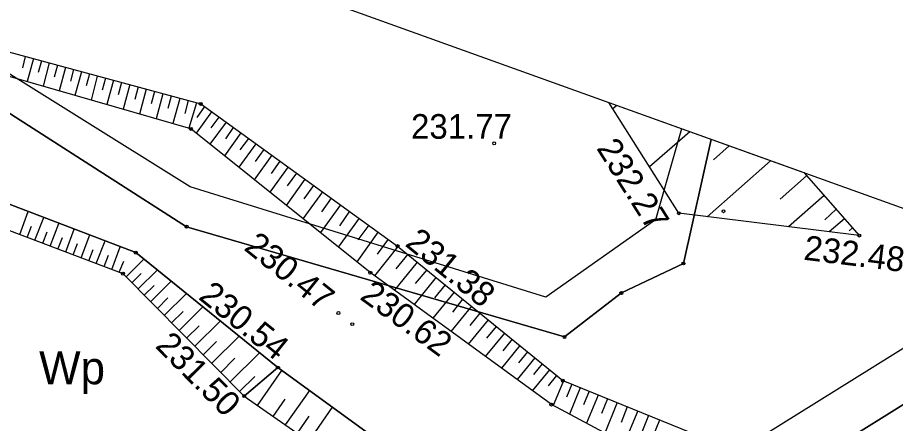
# Model space of a CAD drawing. Extents: x 6596400 to 6597200, y 5539751 to 5540251.
# Drawn here: x 6596761.51 to 6596788.23, y 5540103.13 to 5540115.5 of the extents above; entities that cross this region are included whole.
import ezdxf

# ---------------------------------------------------------------- set-up
doc = ezdxf.new("R2010")
doc.units = 0
for name, color, linetype in [('000 Inne (niezydentyfikowane)', 7, 'Continuous'), ('140-Punkty robocze', 7, 'Continuous'), ('203-punkt graniczny', 7, 'Continuous'), ('210-oznaczenie konturu użytku gruntowego', 7, 'Continuous'), ('217-kontur klasyfikacyjny', 7, 'Continuous'), ('218-kontur użytku gruntowego', 7, 'Continuous'), ('219-działka ewidencyjna', 7, 'Continuous'), ('Linia obszaru zagospodarowania terenu', 7, 'Continuous'), ('pikieta sztuczna', 7, 'Continuous'), ('pikieta sztuczna-Atr2', 7, 'Continuous'), ('skarpa nieumocniona', 7, 'Continuous'), ('skarpa umocniona', 7, 'Continuous'), ('woda płynąca', 7, 'Continuous'), ('Zakres', 7, 'Continuous')]:
    doc.layers.add(name, color=color, linetype=linetype)

# ---------------------------------------------------------------- blocks, each defined once
blk = doc.blocks.new('203')
blk.add_circle((0, 0), 0.045)
blk = doc.blocks.new('PIKIETA')
blk.add_circle((0, 0), 0.045)
blk = doc.blocks.new('PW01')
blk.add_circle((0, 0), 0.045)

msp = doc.modelspace()

# ---------------------------------------------------------------- linework, layer by layer
at = {"layer": '000 Inne (niezydentyfikowane)'}
for p, q in [((6596761.75, 5540114.32), (6596761.66, 5540113.97)), ((6596762, 5540114.25), (6596761.81, 5540113.55)), ((6596762.24, 5540114.18), (6596762.14, 5540113.83)), ((6596762.48, 5540114.12), (6596762.29, 5540113.41)), ((6596762.73, 5540114.05), (6596762.63, 5540113.69)), ((6596762.97, 5540113.98), (6596762.78, 5540113.27)), ((6596763.22, 5540113.92), (6596763.12, 5540113.56)), ((6596763.46, 5540113.85), (6596763.26, 5540113.13)), ((6596763.7, 5540113.79), (6596763.6, 5540113.42)), ((6596763.94, 5540113.72), (6596763.75, 5540112.99)), ((6596764.19, 5540113.66), (6596764.09, 5540113.29)), ((6596764.43, 5540113.59), (6596764.23, 5540112.85)), ((6596764.68, 5540113.52), (6596764.58, 5540113.15)), ((6596764.93, 5540113.46), (6596764.73, 5540112.71)), ((6596765.18, 5540113.39), (6596765.08, 5540113.01)), ((6596765.43, 5540113.32), (6596765.22, 5540112.56)), ((6596765.68, 5540113.25), (6596765.58, 5540112.87)), ((6596765.94, 5540113.18), (6596765.73, 5540112.42)), ((6596766.19, 5540113.11), (6596766.09, 5540112.73)), ((6596766.45, 5540113.04), (6596766.24, 5540112.27)), ((6596766.71, 5540112.97), (6596766.6, 5540112.58)), ((6596766.96, 5540112.9), (6596766.73, 5540112.13)), ((6596767.42, 5540112.63), (6596766.95, 5540111.98)), ((6596767.2, 5540112.79), (6596766.97, 5540112.46)), ((6596779.748, 5540112.823), (6596779.63, 5540112.72)), ((6596767.64, 5540112.47), (6596767.4, 5540112.14)), ((6596767.86, 5540112.31), (6596767.37, 5540111.64)), ((6596768.08, 5540112.15), (6596767.84, 5540111.81)), ((6596768.31, 5540111.99), (6596767.81, 5540111.29)), ((6596768.54, 5540111.82), (6596768.28, 5540111.47)), ((6596781.972, 5540112.024), (6596780.75, 5540110.95)), ((6596768.77, 5540111.65), (6596768.25, 5540110.94)), ((6596783.174, 5540111.591), (6596782.7, 5540111.17)), ((6596769.25, 5540111.31), (6596768.72, 5540110.56)), ((6596769.01, 5540111.48), (6596768.75, 5540111.12)), ((6596769.5, 5540111.13), (6596769.23, 5540110.75)), ((6596784.433, 5540111.138), (6596782.5, 5540109.43)), ((6596769.75, 5540110.95), (6596769.19, 5540110.18)), ((6596770, 5540110.76), (6596769.72, 5540110.37)), ((6596770.26, 5540110.58), (6596769.69, 5540109.78)), ((6596785.53, 5540110.68), (6596784.72, 5540109.97)), ((6596770.79, 5540110.19), (6596770.2, 5540109.37)), ((6596770.52, 5540110.39), (6596770.23, 5540109.98)), ((6596771.06, 5540110), (6596770.76, 5540109.58)), ((6596786.06, 5540110.08), (6596784.98, 5540109.13)), ((6596771.34, 5540109.8), (6596770.73, 5540108.95)), ((6596786.43, 5540109.66), (6596786.08, 5540109.34)), ((6596771.91, 5540109.39), (6596771.27, 5540108.51)), ((6596771.62, 5540109.6), (6596771.31, 5540109.16)), ((6596772.2, 5540109.18), (6596771.87, 5540108.73)), ((6596786.68, 5540109.37), (6596786.22, 5540108.97)), ((6596772.49, 5540108.97), (6596771.84, 5540108.06)), ((6596786.92, 5540109.09), (6596786.82, 5540109)), ((6596772.79, 5540108.75), (6596772.46, 5540108.29)), ((6596773.09, 5540108.53), (6596772.38, 5540107.63)), ((6596773.39, 5540108.29), (6596773.03, 5540107.85)), ((6596773.68, 5540108.05), (6596772.98, 5540107.19)), ((6596773.97, 5540107.82), (6596773.62, 5540107.4)), ((6596774.25, 5540107.59), (6596773.58, 5540106.76)), ((6596774.53, 5540107.36), (6596774.2, 5540106.96)), ((6596774.8, 5540107.14), (6596774.15, 5540106.34)), ((6596775.06, 5540106.92), (6596774.75, 5540106.53)), ((6596775.33, 5540106.71), (6596774.7, 5540105.94)), ((6596775.58, 5540106.5), (6596775.28, 5540106.12)), ((6596775.84, 5540106.29), (6596775.23, 5540105.55)), ((6596776.08, 5540106.09), (6596775.79, 5540105.73)), ((6596776.33, 5540105.89), (6596775.75, 5540105.18)), ((6596776.57, 5540105.7), (6596776.28, 5540105.35)), ((6596776.8, 5540105.51), (6596776.24, 5540104.82)), ((6596777.26, 5540105.13), (6596776.72, 5540104.47)), ((6596777.03, 5540105.32), (6596776.76, 5540104.98)), ((6596777.48, 5540104.95), (6596777.22, 5540104.63)), ((6596777.7, 5540104.77), (6596777.18, 5540104.13)), ((6596777.92, 5540104.6), (6596777.66, 5540104.28)), ((6596778.13, 5540104.43), (6596777.82, 5540103.68)), ((6596778.38, 5540104.33), (6596778.22, 5540103.94)), ((6596778.64, 5540104.22), (6596778.31, 5540103.42)), ((6596778.91, 5540104.12), (6596778.74, 5540103.7)), ((6596779.18, 5540104), (6596778.83, 5540103.14)), ((6596779.47, 5540103.89), (6596779.29, 5540103.44)), ((6596779.76, 5540103.77), (6596779.39, 5540102.84)), ((6596780.07, 5540103.64), (6596779.88, 5540103.16)), ((6596780.39, 5540103.52), (6596779.98, 5540102.52)), ((6596780.72, 5540103.38), (6596780.51, 5540102.87)), ((6596781.05, 5540103.24), (6596780.62, 5540102.18))]:
    msp.add_line(p, q, dxfattribs=at)
for points in [[(6596761.58, 5540108.89), (6596761.84, 5540109.59)], [(6596762.04, 5540108.72), (6596762.31, 5540109.41)], [(6596761.81, 5540108.8), (6596761.94, 5540109.15)], [(6596762.51, 5540108.54), (6596762.77, 5540109.23)], [(6596762.28, 5540108.63), (6596762.41, 5540108.97)], [(6596762.98, 5540108.36), (6596763.24, 5540109.05)], [(6596763.45, 5540108.18), (6596763.71, 5540108.88)], [(6596762.74, 5540108.45), (6596762.88, 5540108.8)], [(6596763.21, 5540108.27), (6596763.34, 5540108.62)], [(6596763.91, 5540108.01), (6596764.18, 5540108.7)], [(6596763.68, 5540108.09), (6596763.81, 5540108.44)], [(6596764.38, 5540107.83), (6596764.64, 5540108.52)], [(6596764.15, 5540107.92), (6596764.28, 5540108.26)], [(6596764.61, 5540107.74), (6596764.75, 5540108.08)], [(6596764.82, 5540107.6), (6596765.36, 5540108.14)], [(6596765.18, 5540107.24), (6596765.76, 5540107.81)], [(6596764.99, 5540107.42), (6596765.28, 5540107.7)], [(6596765.37, 5540107.04), (6596765.67, 5540107.34)], [(6596765.57, 5540106.85), (6596766.19, 5540107.47)], [(6596765.98, 5540106.42), (6596766.66, 5540107.09)], [(6596765.77, 5540106.64), (6596766.09, 5540106.96)], [(6596766.2, 5540106.2), (6596766.55, 5540106.55)], [(6596766.43, 5540105.97), (6596767.15, 5540106.69)], [(6596766.91, 5540105.49), (6596767.69, 5540106.26)], [(6596766.66, 5540105.73), (6596767.04, 5540106.11)], [(6596767.43, 5540104.97), (6596768.26, 5540105.79)], [(6596767.16, 5540105.23), (6596767.57, 5540105.63)], [(6596767.7, 5540104.69), (6596768.13, 5540105.12)], [(6596767.98, 5540104.4), (6596768.88, 5540105.29)], [(6596768.82, 5540103.68), (6596769.56, 5540104.75)], [(6596768.27, 5540104.11), (6596768.74, 5540104.57)], [(6596769.67, 5540103.09), (6596770.41, 5540104.14)], [(6596769.29, 5540103.35), (6596769.66, 5540103.88)], [(6596770.38, 5540102.59), (6596771.1, 5540103.63)], [(6596770.03, 5540102.84), (6596770.39, 5540103.36)]]:
    msp.add_lwpolyline(points, dxfattribs=at)
at = {"layer": '217-kontur klasyfikacyjny'}
for points in [[(6596757.03, 5540115.3), (6596766.66, 5540109.13)], [(6596781.78, 5540108.01), (6596782.625, 5540111.789)], [(6596766.66, 5540109.13), (6596778.16, 5540105.77)], [(6596779.89, 5540107.11), (6596781.78, 5540108.01)], [(6596778.16, 5540105.77), (6596779.89, 5540107.11)], [(6596791.43, 5540105.56), (6596776.03, 5540095.93)]]:
    msp.add_lwpolyline(points, dxfattribs=at)
at = {"layer": '218-kontur użytku gruntowego'}
for points in [[(6596757.03, 5540115.3), (6596766.66, 5540109.13)], [(6596766.66, 5540109.13), (6596757.03, 5540115.3)], [(6596781.78, 5540108.01), (6596782.625, 5540111.789)], [(6596782.625, 5540111.789), (6596781.78, 5540108.01)], [(6596766.66, 5540109.13), (6596778.16, 5540105.77)], [(6596778.16, 5540105.77), (6596766.66, 5540109.13)], [(6596779.89, 5540107.11), (6596781.78, 5540108.01)], [(6596781.78, 5540108.01), (6596779.89, 5540107.11)], [(6596778.16, 5540105.77), (6596779.89, 5540107.11)], [(6596779.89, 5540107.11), (6596778.16, 5540105.77)], [(6596776.03, 5540095.93), (6596791.43, 5540105.56)], [(6596791.43, 5540105.56), (6596776.03, 5540095.93)]]:
    msp.add_lwpolyline(points, dxfattribs=at)
at = {"layer": '219-działka ewidencyjna'}
for points in [[(6596766.66, 5540109.13), (6596757.03, 5540115.3)], [(6596781.78, 5540108.01), (6596782.625, 5540111.789)], [(6596778.16, 5540105.77), (6596766.66, 5540109.13)], [(6596779.89, 5540107.11), (6596781.78, 5540108.01)], [(6596778.16, 5540105.77), (6596779.89, 5540107.11)], [(6596776.03, 5540095.93), (6596791.43, 5540105.56)]]:
    msp.add_lwpolyline(points, dxfattribs=at)
at = {"layer": 'Linia obszaru zagospodarowania terenu'}
for points in [[(6596781.725, 5540112.112), (6596780.93, 5540109.34), (6596777.59, 5540106.98), (6596766.77, 5540110.34), (6596752.84, 5540119.06), (6596742.54, 5540110.89), (6596731.18, 5540096.66), (6596730.7, 5540082.79)], [(6596746.77, 5540082.74), (6596749.37, 5540097.92), (6596757.81, 5540103.76), (6596775.58, 5540097.4), (6596790.99, 5540107), (6596791.128, 5540108.731)]]:
    msp.add_lwpolyline(points, dxfattribs=at)
at = {"layer": 'skarpa nieumocniona'}
for points in [[(6596736.14, 5540074.83), (6596735.19, 5540080.23), (6596735.33, 5540085.41), (6596734.65, 5540089.1), (6596735.44, 5540093.45), (6596735.8, 5540095.62), (6596737, 5540098.15), (6596738.35, 5540109.49), (6596736.12, 5540109.87), (6596735.6, 5540111.55), (6596739.06, 5540111.12), (6596739.7, 5540112.38), (6596741.35, 5540114.97), (6596743.9, 5540116.21), (6596748.71, 5540116.3), (6596760.37, 5540114.69), (6596767.09, 5540112.87), (6596773.08, 5540108.54), (6596778.11, 5540104.44), (6596785.94, 5540101.26), (6596790.69, 5540099.45)], [(6596736.14, 5540074.83), (6596735.19, 5540080.23), (6596735.33, 5540085.41), (6596734.65, 5540089.1), (6596735.44, 5540093.45), (6596735.8, 5540095.62), (6596737, 5540098.15), (6596738.35, 5540109.49), (6596736.12, 5540109.87), (6596735.6, 5540111.55), (6596739.06, 5540111.12), (6596739.7, 5540112.38), (6596741.35, 5540114.97), (6596743.9, 5540116.21), (6596748.71, 5540116.3), (6596760.37, 5540114.69), (6596767.09, 5540112.87), (6596773.08, 5540108.54), (6596778.11, 5540104.44), (6596785.94, 5540101.26), (6596790.69, 5540099.45)], [(6596790.15, 5540098.33), (6596785.05, 5540099.81), (6596777.76, 5540103.71), (6596772.25, 5540107.73), (6596766.79, 5540112.11), (6596760.34, 5540113.97), (6596748.88, 5540115.79), (6596744.15, 5540115.57), (6596742.04, 5540114.13), (6596740.39, 5540112.04), (6596739.35, 5540110.21), (6596737.64, 5540097.87), (6596736.29, 5540093.37), (6596736.04, 5540089.3), (6596736.53, 5540085.88), (6596736.56, 5540080.1), (6596736.48, 5540078.77)], [(6596790.15, 5540098.33), (6596785.05, 5540099.81), (6596777.76, 5540103.71), (6596772.25, 5540107.73), (6596766.79, 5540112.11), (6596760.34, 5540113.97), (6596748.88, 5540115.79), (6596744.15, 5540115.57), (6596742.04, 5540114.13), (6596740.39, 5540112.04), (6596739.35, 5540110.21), (6596737.64, 5540097.87), (6596736.29, 5540093.37), (6596736.04, 5540089.3), (6596736.53, 5540085.88), (6596736.56, 5540080.1), (6596736.48, 5540078.77)]]:
    msp.add_lwpolyline(points, dxfattribs=at)
for points in [[(6596785.44, 5540110.78), (6596787.13, 5540108.86), (6596781.64, 5540109.54), (6596779.51, 5540112.91)], [(6596785.44, 5540110.78), (6596787.13, 5540108.86), (6596781.64, 5540109.54), (6596779.51, 5540112.91)], [(6596742.42, 5540096.36), (6596740.92, 5540088.42), (6596741.25, 5540084.94), (6596741.25, 5540084.94), (6596742.75, 5540092.05), (6596743.5, 5540096.22), (6596744.79, 5540102.47), (6596745.19, 5540106.93), (6596748.55, 5540109.04), (6596750.9, 5540110.05), (6596759.79, 5540109.57), (6596764.72, 5540107.7), (6596768.41, 5540103.97), (6596769.44, 5540104.84), (6596765.11, 5540108.34), (6596759.95, 5540110.31), (6596750.9, 5540111.08), (6596747.66, 5540110.25), (6596744.49, 5540107.55), (6596743.6, 5540103.66)], [(6596742.42, 5540096.36), (6596740.92, 5540088.42), (6596741.25, 5540084.94), (6596741.25, 5540084.94), (6596742.75, 5540092.05), (6596743.5, 5540096.22), (6596744.79, 5540102.47), (6596745.19, 5540106.93), (6596748.55, 5540109.04), (6596750.9, 5540110.05), (6596759.79, 5540109.57), (6596764.72, 5540107.7), (6596768.41, 5540103.97), (6596769.44, 5540104.84), (6596765.11, 5540108.34), (6596759.95, 5540110.31), (6596750.9, 5540111.08), (6596747.66, 5540110.25), (6596744.49, 5540107.55), (6596743.6, 5540103.66)]]:
    msp.add_lwpolyline(points, close=True, dxfattribs=at)
at = {"layer": 'skarpa umocniona'}
msp.add_lwpolyline([(6596768.41, 5540103.97), (6596776.33, 5540098.44), (6596782, 5540095.31), (6596783.42, 5540094.18), (6596788.65, 5540093.09), (6596792.84, 5540092.11), (6596803.9, 5540094.29), (6596790.43, 5540094.51), (6596783.39, 5540096.06), (6596775.99, 5540100.07), (6596769.44, 5540104.84)], close=True, dxfattribs=at)
msp.add_lwpolyline([(6596768.41, 5540103.97), (6596776.33, 5540098.44), (6596782, 5540095.31), (6596783.42, 5540094.18), (6596788.65, 5540093.09), (6596792.84, 5540092.11), (6596803.9, 5540094.29), (6596790.43, 5540094.51), (6596783.39, 5540096.06), (6596775.99, 5540100.07), (6596769.44, 5540104.84)], close=True, dxfattribs=at)
at = {"layer": 'woda płynąca'}
for points in [[(6596801.146, 5540105.126), (6596800.55, 5540103.15), (6596798.59, 5540101.49), (6596797.54, 5540099.56), (6596796.12, 5540099.28), (6596790.15, 5540098.33), (6596785.05, 5540099.81), (6596777.76, 5540103.71), (6596772.25, 5540107.73), (6596766.79, 5540112.11), (6596760.34, 5540113.97), (6596748.88, 5540115.79), (6596744.15, 5540115.57), (6596742.04, 5540114.13), (6596740.39, 5540112.04), (6596739.35, 5540110.21), (6596737.64, 5540097.87), (6596736.29, 5540093.37), (6596736.04, 5540089.3), (6596736.53, 5540085.88)], [(6596746.88, 5540042.02), (6596743.2, 5540046.89), (6596742.01, 5540050.53), (6596741.65, 5540054.82), (6596742.47, 5540061.97), (6596743.25, 5540066.3), (6596741.68, 5540074.92), (6596740.68, 5540078.45), (6596740.72, 5540079.85), (6596740.91, 5540084.82), (6596741.25, 5540084.94), (6596740.92, 5540088.42), (6596742.42, 5540096.36), (6596743.6, 5540103.66), (6596744.49, 5540107.55), (6596747.66, 5540110.25), (6596750.9, 5540111.08), (6596759.95, 5540110.31), (6596765.11, 5540108.34), (6596769.44, 5540104.84), (6596775.99, 5540100.07), (6596783.39, 5540096.06), (6596790.43, 5540094.51)]]:
    msp.add_lwpolyline(points, dxfattribs=at)
at = {"layer": 'Zakres'}
msp.add_lwpolyline([(6596822.22, 5540097.5), (6596800.39, 5540105.4), (6596755.76, 5540121.45), (6596697.73, 5540120.74), (6596659.35, 5540133.92), (6596647.64, 5540109.28), (6596697.73, 5540077), (6596721.01, 5540057.77), (6596727.72, 5540045.95), (6596731.95, 5540033.61), (6596741.17, 5540031.18), (6596755.59, 5540029.2), (6596757.85, 5540044.22), (6596787.25, 5540055.04), (6596806.3, 5540048.33), (6596813.97, 5540042.6), (6596833.15, 5540068.58), (6596822.3, 5540077.75)], close=True, dxfattribs=at)

# ---------------------------------------------------------------- block references
at = {"layer": '140-Punkty robocze'}
for p in [(6596767.09, 5540112.87), (6596766.79, 5540112.11), (6596776.02, 5540111.67), (6596781.64, 5540109.54), (6596783, 5540109.6), (6596787.13, 5540108.86), (6596773.08, 5540108.54), (6596765.11, 5540108.34), (6596764.72, 5540107.7), (6596772.25, 5540107.73), (6596771.28, 5540106.5), (6596771.7, 5540106.16), (6596769.44, 5540104.84), (6596778.11, 5540104.44), (6596768.41, 5540103.97), (6596777.76, 5540103.71)]:
    msp.add_blockref('PIKIETA', p, dxfattribs=at)
at = {"layer": '203-punkt graniczny'}
for p in [(6596766.66, 5540109.13), (6596781.78, 5540108.01), (6596779.89, 5540107.11), (6596778.16, 5540105.77)]:
    msp.add_blockref('203', p, dxfattribs=at)
at = {"layer": 'pikieta sztuczna'}
for p in [(6596776.02, 5540111.67), (6596781.64, 5540109.54), (6596787.13, 5540108.86), (6596773.08, 5540108.54), (6596772.25, 5540107.73), (6596771.28, 5540106.5), (6596769.44, 5540104.84), (6596768.41, 5540103.97)]:
    msp.add_blockref('PW01', p, dxfattribs=at)

# ---------------------------------------------------------------- texts
at = {"layer": '210-oznaczenie konturu użytku gruntowego'}
msp.add_text('Wp', height=1, dxfattribs=at).set_placement((6596762.17, 5540104.33))
at = {"layer": 'pikieta sztuczna-Atr2'}
msp.add_text('231.77', height=0.75, dxfattribs=at).set_placement((6596773.49, 5540111.81))
for s, rotation, p in [('232.27', 302.261, (6596779.116, 5540111.52)), ('230.47', 321.263, (6596768.371, 5540108.445)), ('231.38', 320.816, (6596773.276, 5540108.569)), ('232.48', 352.939, (6596785.418, 5540108.126)), ('230.54', 321.051, (6596766.989, 5540106.947)), ('230.62', 323.886, (6596771.898, 5540106.944)), ('231.50', 314.691, (6596765.677, 5540105.473))]:
    msp.add_text(s, height=0.75, rotation=rotation, dxfattribs=at).set_placement(p)

doc.saveas('drawing.dxf')
